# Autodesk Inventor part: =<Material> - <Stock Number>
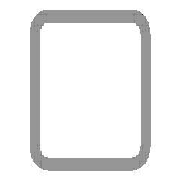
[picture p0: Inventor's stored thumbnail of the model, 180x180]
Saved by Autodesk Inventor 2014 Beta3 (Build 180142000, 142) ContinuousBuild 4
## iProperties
IsCustomPart: 1
_CCFamilyMember: 9
_CCFamilyDisplayName: ANSI AISC (Square) - Tube
_FrameMemberDoc: Frame Member File
_Version: 15.0.0
_GetPNFromCC: 1
Created: 2011-01
Part Number: =<Material> - <Stock Number>
Material: Steel, Mild
Description: Tube
Document SubType Name: Modeling
Standard: ANSI
Designer: Beta-8540w
Standards Organization: ANSI
Language: en-US
Size Designation: 3x3x3/16
Categories: <MemberInstance><Categories><Category DisplayName="Structural Shapes" InternalName="089c4875-fa83-4c05-b084-43b9cc11f5ed" Mnemonic="GRDR"><CategoryParameter Dis
Stock Number: 3x3x3/16
Density: 7.86 g/cm^3
Appearance: Steel
G_L: 58.775 in
G_W: 3.000 in
G_H: 3.000 in
+AE3CA65D-4403-45DE-BD14-7280831DFD21+CUTDETAIL1: Cut
Author: Beta-8540w
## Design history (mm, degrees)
node "Start plane"
node "End plane"
sketch "Sketch"
  geometry: L1 (-38.1, -28.575)-(-38.1, 28.575); L2 (-28.575, 38.1)-(28.575, 38.1); L3 (38.1, 28.575)-(38.1, -28.575); L4 (28.575, -38.1)-(-28.575, -38.1); L5 (-28.575, 33.337)-(28.575, 33.338); L6 (33.338, 28.575)-(33.338, -28.575); L7 (28.575, -33.337)-(-28.575, -33.338); L8 (-33.338, -28.575)-(-33.338, 28.575); L9 (0, 56.102)-(0, -56.102) reference; L10 (-56.102, 0)-(56.102, 0) reference; A1 r 9.525 centre (-28.575, -28.575) between (-38.1, -28.575) and (-28.575, -38.1); A2 r 9.525 centre (-28.575, 28.575) between (-28.575, 38.1) and (-38.1, 28.575); A3 r 9.525 centre (28.575, 28.575) between (38.1, 28.575) and (28.575, 38.1); A4 r 9.525 centre (28.575, -28.575) between (28.575, -38.1) and (38.1, -28.575); A5 r 4.763 centre (-28.575, 28.575) between (-28.575, 33.337) and (-33.338, 28.575); A6 r 4.763 centre (28.575, 28.575) between (33.338, 28.575) and (28.575, 33.338); A7 r 4.763 centre (28.575, -28.575) between (28.575, -33.337) and (33.338, -28.575); A8 r 4.763 centre (-28.575, -28.575) between (-33.338, -28.575) and (-28.575, -33.338)
  constraints: 16 end point, 16 point on circle, 8 centre point, 8 tangent, 4 parallel, 3 equal radius, 2 perpendicular, 7 other
  dimensions: "d10" = 76.2 distance between parallel lines of L2 L4 (= G_H); "d11" = 76.2 distance between parallel lines of L1 L3 (= G_W); "d12" = 4.7625 distance between parallel lines of L3 L6 (= G_T); "d15" = 38.1 distance between parallel lines of L2 L10 (= 0.5 x d10); "d16" = 38.1 distance between parallel lines of L9 L3 (= 0.5 x d11); "d17" = 9.525 radius of A1 (= G_IR)
extrude "Body" new body sketch "Sketch" stored distance "d3" = 1492.89148 (= G_L); taper "d4" = 0 deg
node "Driven Length"
  sketch "Sketch3"
    geometry: L1 (0, 0)-(10, 0) reference
    constraints: 2 end point, 1 horizontal
  workplane "Work Plane3"
  sketch "Sketch4"
    geometry: L1 (-2, 0)-(12, 0) reference; L2 (-2, 1492.891)-(12, 1492.891) reference
    dimensions: "d19" = 1492.89148 distance between parallel lines of L1 L2 (derived)
workplane "Work Plane4"
split "Split1"
body "Solid1"
other parameters: "G_W" = 76.2 [user parameter; used in 1 equation term], "G_H" = 76.2 [user parameter; used in 1 equation term], "G_T" = 4.7625 [user parameter; used in 1 equation term], "G_IR" = 9.525 [user parameter; used in 1 equation term], "G_L" = 1492.89148 (= d19) [user parameter; used in 1 equation term], "G_OFFSET_START" = 0 [user parameter; used in 1 equation term], "G_OFFSET_END" = -31.10852 [user parameter; used in 1 equation term], "d13" = 0 (computed from G_OFFSET_START), "d14" = 1492.89148 (= G_OFFSET_END + B_L), "B_L" = 1524 [user parameter; used in 1 equation term], "d18" = 90 deg
